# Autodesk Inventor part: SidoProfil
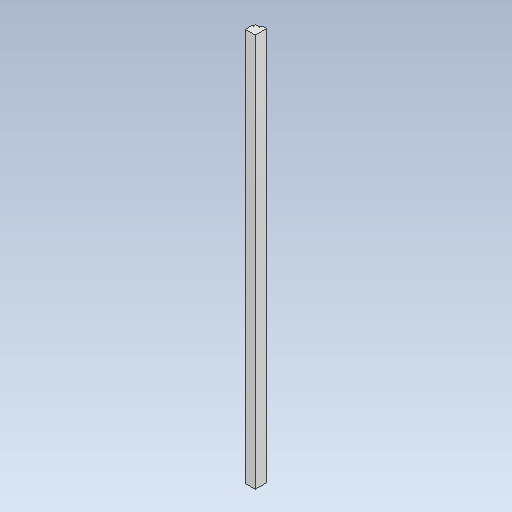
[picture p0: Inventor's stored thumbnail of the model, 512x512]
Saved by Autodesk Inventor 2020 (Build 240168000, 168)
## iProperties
Created: 2019-06
Part Number: SidoProfil
Material: Aluminum
Document SubType Name: Modeling
Designer: cl
Density: 2.7 g/cm^3
Appearance: Satin
Author: cl
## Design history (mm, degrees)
sketch "Sketch1"
  geometry: L1 (0, 0)-(87, 0); L2 (87, 0)-(87, -60); L3 (87, -60)-(77, -60); L4 (77, -60)-(77, -80); L5 (77, -80)-(40, -80); L6 (40, -80)-(40, -100); L7 (40, -100)-(0, -100); L8 (0, -100)-(0, 0)
  constraints: 16 end point, 5 perpendicular, 2 horizontal
  dimensions: "d0" = 87 distance of L1.start L1.end; "d1" = 60 distance of L1.end L2.end; "d2" = 10 distance of L2.end L3.end; "d3" = 20 distance of L3.end L4.end; "d4" = 37 distance of L4.end L5.end; "d5" = 20 distance of L5.end L6.end; "d6" = 40 distance of L6.end L7.end
extrude "Extrusion1" new body sketch "Sketch1" distance "d7" = 3444 (computed from Daghöjd); taper "d8" = 0 deg
body "Solid1"
other parameters: "Daghöjd" = 3254, "Dagbredd" = 2222
